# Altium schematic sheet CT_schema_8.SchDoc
size 287 x 160 mm
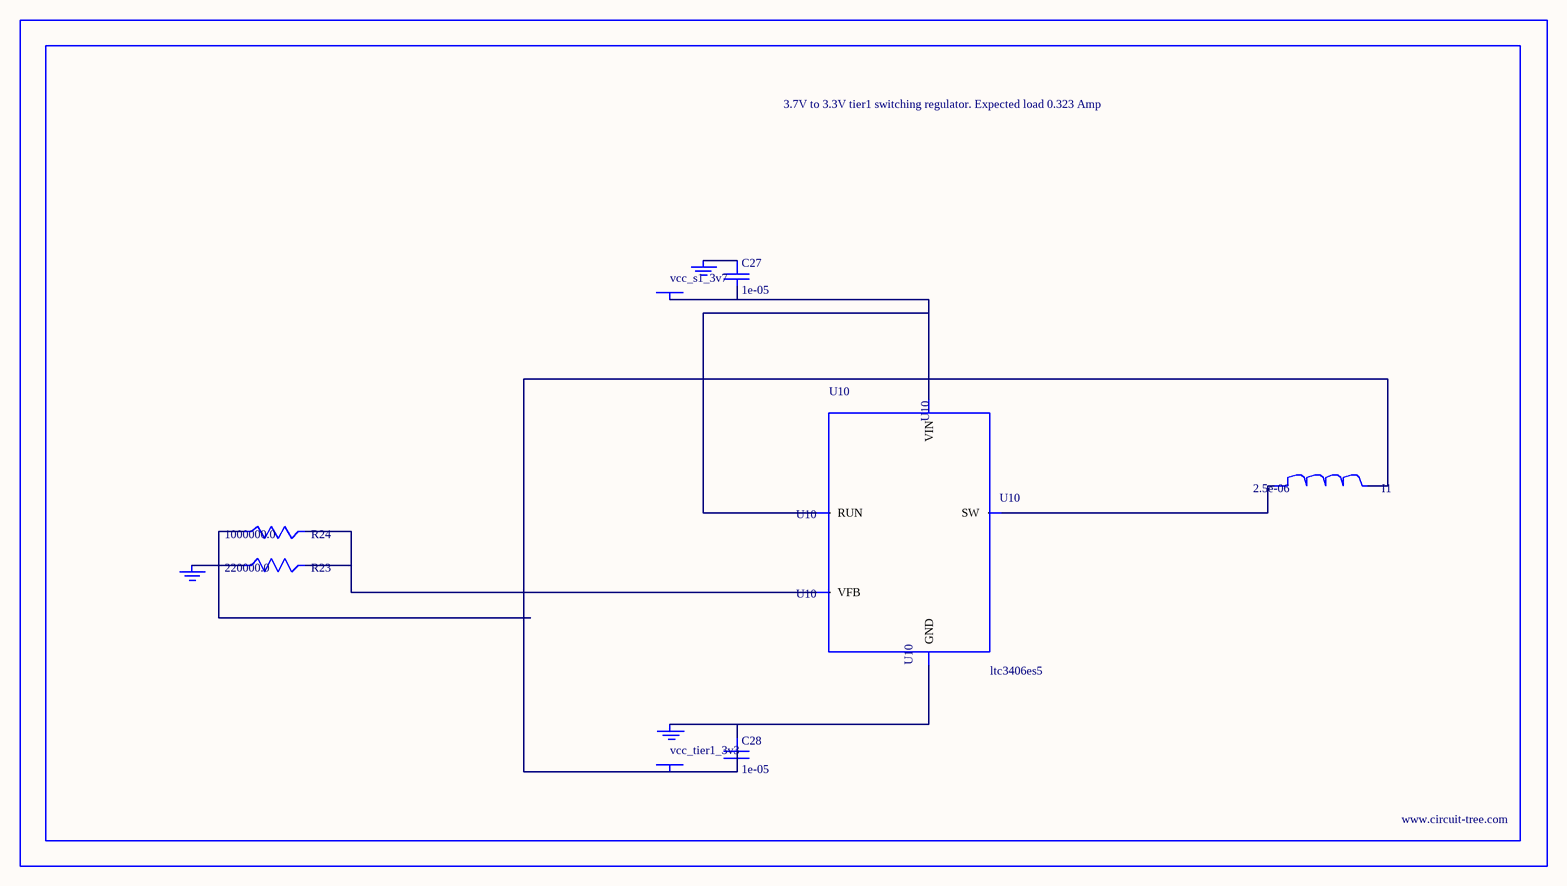
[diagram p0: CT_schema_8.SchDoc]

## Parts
BORDER7  (no value)
C27  1e-05  [C0805]
C28  1e-05  [C0805]
GND_INSTANCE_7_0  (no value)
GND_INSTANCE_7_1  (no value)
GND_INSTANCE_7_2  (no value)
I1  2.5e-06  [DR1040]
POWER_INSTANCE_7_0  vcc_tier1_3v3
POWER_INSTANCE_7_1  vcc_s1_3v7
R23  220000.0  [R0603]
R24  1000000.0  [R0603]
U10  ltc3406es5  [TSOT-23-5]

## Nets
NetC27_1: C27.1 GND_INSTANCE_7_1.0(GND)
NetC27_2: C27.2 POWER_INSTANCE_7_1.0(PWR) U10.1(RUN) U10.4(VIN)
NetC28_1: C28.1 GND_INSTANCE_7_0.0(GND) U10.2(GND)
NetC28_2: C28.2 I1.2 POWER_INSTANCE_7_0.0(PWR) R24.1
NetGND_INSTANCE_7_2_0: GND_INSTANCE_7_2.0(GND) R23.1
NetI1_1: I1.1 U10.3(SW)
NetR23_2: R23.2 R24.2 U10.5(VFB)

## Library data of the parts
BORDER7 = BORDER_PAGE7
C27 C28 = C0805C106K8RACTU
GND_INSTANCE_7_0-GND_INSTANCE_7_2 = GND
I1 = DR1040-2R5-R
POWER_INSTANCE_7_0 POWER_INSTANCE_7_1 = PWR
R23 = RC0603JR-07220KL
R24 = RC0603JR-071ML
